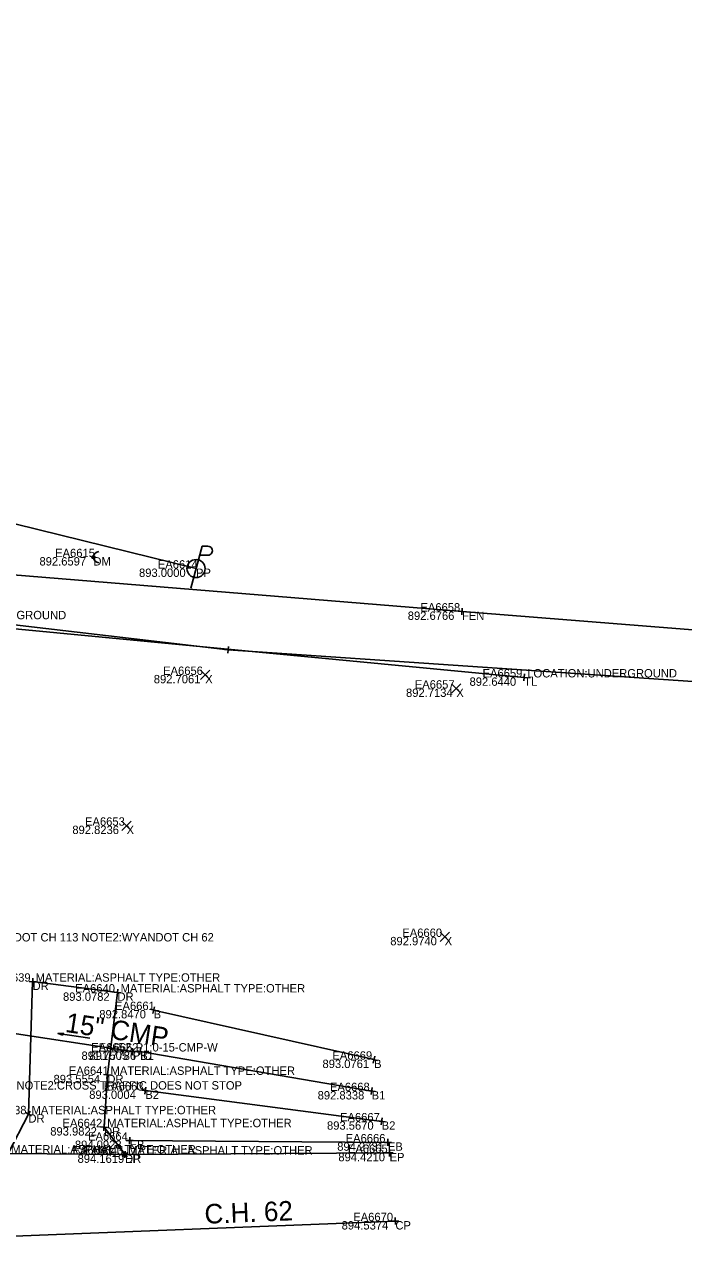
# Model space of a CAD drawing. Extents: x 179044 to 189691, y 286531 to 301257.
# Drawn here: x 180439.4 to 180533.9, y 300591.3 to 300769 of the extents above; entities that cross this region are included whole.
import ezdxf

# ---------------------------------------------------------------- set-up
doc = ezdxf.new("R2010")
doc.units = 0
for name, color, linetype in [('Default', 7, 'Continuous'), ('DR_X_Elev_Flow', 7, 'Continuous'), ('DR_X_Storm_Sewer', 7, 'Continuous'), ('DR_X_Text', 7, 'Continuous'), ('GK_Visualization', 7, 'Continuous'), ('PV_X_COP', 7, 'Continuous'), ('PV_X_Driveway', 7, 'Continuous'), ('PV_X_EOP', 7, 'Continuous'), ('PV_X_Shoulder_Aggregate', 7, 'Continuous'), ('RD_X_Fence', 7, 'Continuous'), ('SV_X_Break_Lines', 7, 'Continuous'), ('SV_X_Random_Point', 7, 'Continuous'), ('SV_X_Shot_Marker', 7, 'Continuous'), ('SV_X_Text_Comment', 7, 'Continuous'), ('SV_X_Text_Description', 7, 'Continuous'), ('SV_X_Text_Elevation', 7, 'Continuous'), ('SV_X_Text_Name', 7, 'Continuous'), ('UT_X_Electric', 7, 'Continuous'), ('UT_X_Electric_Cells', 7, 'Continuous'), ('UT_X_Misc_Cells', 7, 'Continuous'), ('UT_X_Telecom', 7, 'Continuous')]:
    doc.layers.add(name, color=color, linetype=linetype)

msp = doc.modelspace()

# ---------------------------------------------------------------- linework, layer by layer
at = {"layer": 'DR_X_Elev_Flow'}
for p, q in [((180454.37, 300621.65), (180455.37, 300621.65)), ((180454.85, 300621.65), (180454.9, 300621.65)), ((180454.87, 300622.15), (180454.87, 300621.15)), ((180454.87, 300621.68), (180454.87, 300621.63)), ((180454.87, 300621.65), (180454.87, 300621.65)), ((180454.87, 300621.65), (180454.87, 300621.65))]:
    msp.add_line(p, q, dxfattribs=at)
at = {"layer": 'DR_X_Storm_Sewer'}
msp.add_line((180454.87, 300621.65), (180427.21, 300625.82), dxfattribs=at)
at = {"layer": 'DR_X_Text'}
msp.add_line((180448.74, 300623.56), (180444.18, 300624.25), dxfattribs=at)
msp.add_lwpolyline([(180444.85, 300624), (180444.9, 300624.29), (180444.18, 300624.25)], close=True, dxfattribs=at)
at = {"layer": 'GK_Visualization'}
msp.add_line((180492.59, 300597.31), (180492.59, 300597.31), dxfattribs=at)
at = {"layer": 'PV_X_COP'}
msp.add_line((180492.59, 300597.31), (180492.59, 300597.31), dxfattribs=at)
msp.add_lwpolyline([(180387.7, 300594.07), (180431.76, 300594.91), (180492.59, 300597.31)], dxfattribs=at)
at = {"layer": 'PV_X_Driveway'}
msp.add_lwpolyline([(180437.01, 300607.02), (180439.92, 300612.65), (180440.51, 300631.67), (180452.7, 300630.12), (180451.25, 300618.3), (180450.77, 300610.79), (180453.78, 300606.87)], dxfattribs=at)
at = {"layer": 'PV_X_EOP'}
msp.add_lwpolyline([(180336.02, 300768.96), (180371.12, 300675.18), (180391.48, 300627.03), (180401.14, 300618.13), (180409.94, 300612.3), (180420.83, 300608.19), (180437.01, 300607.02), (180453.78, 300606.87), (180491.75, 300607.1)], dxfattribs=at)
at = {"layer": 'PV_X_Shoulder_Aggregate'}
msp.add_lwpolyline([(180454.44, 300608.87), (180491.51, 300608.61)], dxfattribs=at)
at = {"layer": 'RD_X_Fence'}
for points in [[(180413.11, 300692.06), (180502.15, 300684.78)], [(180502.15, 300684.78), (180578.58, 300678.71), (180657.49, 300671.91), (180764.58, 300663.83), (180831.65, 300658.07), (180898.21, 300649.16), (180980.03, 300636.76), (181057.42, 300625.97)]]:
    msp.add_lwpolyline(points, dxfattribs=at)
at = {"layer": 'SV_X_Break_Lines'}
for points in [[(180457.89, 300627.6), (180489.53, 300620.48)], [(180455.96, 300621.64), (180489.18, 300615.97)], [(180456.7, 300616.05), (180490.62, 300611.63)]]:
    msp.add_lwpolyline(points, dxfattribs=at)
at = {"layer": 'SV_X_Random_Point'}
for p, q in [((180464.62, 300675.02), (180465.95, 300676.35)), ((180464.62, 300676.35), (180465.95, 300675.02)), ((180500.66, 300673.05), (180502, 300674.39)), ((180500.66, 300674.39), (180502, 300673.05)), ((180453.33, 300653.38), (180454.67, 300654.72)), ((180453.33, 300654.72), (180454.67, 300653.38)), ((180498.99, 300637.42), (180500.33, 300638.76)), ((180498.99, 300638.76), (180500.33, 300637.42))]:
    msp.add_line(p, q, dxfattribs=at)
at = {"layer": 'SV_X_Shot_Marker'}
for p, q in [((180501.65, 300684.82), (180502.65, 300684.74)), ((180502.19, 300685.28), (180502.11, 300684.28)), ((180502.15, 300684.78), (180502.15, 300684.78)), ((180468.08, 300679.34), (180469.08, 300679.22)), ((180468.64, 300679.78), (180468.52, 300678.78)), ((180468.58, 300679.28), (180468.58, 300679.28)), ((180510.58, 300675.37), (180511.57, 300675.27)), ((180511.12, 300675.82), (180511.03, 300674.82)), ((180511.07, 300675.32), (180511.07, 300675.32)), ((180440.5, 300631.17), (180440.53, 300632.17)), ((180440.01, 300631.69), (180441.01, 300631.65)), ((180440.51, 300631.67), (180440.51, 300631.67)), ((180452.77, 300630.61), (180452.64, 300629.62)), ((180452.21, 300630.18), (180453.2, 300630.05)), ((180452.7, 300630.12), (180452.7, 300630.12)), ((180457.4, 300627.71), (180458.38, 300627.49)), ((180458, 300628.08), (180457.78, 300627.11)), ((180457.89, 300627.6), (180457.89, 300627.6)), ((180455.47, 300621.73), (180456.45, 300621.56)), ((180456.05, 300622.13), (180455.88, 300621.15)), ((180455.96, 300621.64), (180455.96, 300621.64)), ((180489.04, 300620.59), (180490.02, 300620.37)), ((180489.64, 300620.97), (180489.42, 300619.99)), ((180489.53, 300620.48), (180489.53, 300620.48)), ((180451.75, 300618.24), (180450.76, 300618.36)), ((180451.31, 300618.8), (180451.19, 300617.8)), ((180451.25, 300618.3), (180451.25, 300618.3)), ((180456.21, 300616.11), (180457.2, 300615.98)), ((180456.77, 300616.54), (180456.64, 300615.55)), ((180489.26, 300616.47), (180489.1, 300615.48)), ((180456.7, 300616.05), (180456.7, 300616.05)), ((180488.69, 300616.06), (180489.67, 300615.89)), ((180489.18, 300615.97), (180489.18, 300615.97)), ((180439.48, 300612.88), (180440.37, 300612.42)), ((180439.69, 300612.21), (180440.15, 300613.1)), ((180439.92, 300612.65), (180439.92, 300612.65)), ((180451.27, 300610.76), (180450.28, 300610.82)), ((180450.81, 300611.29), (180450.74, 300610.29)), ((180450.77, 300610.79), (180450.77, 300610.79)), ((180490.12, 300611.7), (180491.11, 300611.57)), ((180490.68, 300612.13), (180490.55, 300611.14)), ((180490.62, 300611.63), (180490.62, 300611.63)), ((180454.45, 300609.37), (180454.44, 300608.37)), ((180491.51, 300609.11), (180491.51, 300608.11)), ((180453.47, 300607.26), (180454.08, 300606.47)), ((180453.78, 300607.37), (180453.77, 300606.37)), ((180453.94, 300608.88), (180454.94, 300608.87)), ((180454.44, 300608.87), (180454.44, 300608.87)), ((180491.01, 300608.61), (180492.01, 300608.6)), ((180491.51, 300608.61), (180491.51, 300608.61)), ((180491.75, 300607.6), (180491.76, 300606.6)), ((180453.28, 300606.87), (180454.28, 300606.86)), ((180454.17, 300607.17), (180453.38, 300606.56)), ((180453.78, 300606.87), (180453.78, 300606.87)), ((180453.78, 300606.87), (180453.78, 300606.87)), ((180491.25, 300607.1), (180492.25, 300607.11)), ((180491.75, 300607.1), (180491.75, 300607.1)), ((180493.09, 300597.33), (180492.09, 300597.29)), ((180492.61, 300596.81), (180492.57, 300597.81)), ((180492.59, 300597.31), (180492.59, 300597.31))]:
    msp.add_line(p, q, dxfattribs=at)
at = {"layer": 'UT_X_Electric'}
msp.add_lwpolyline([(180111.81, 300685.43), (180395.56, 300707.8), (180463.97, 300690.94)], dxfattribs=at)
at = {"layer": 'UT_X_Electric_Cells'}
for p, q in [((180464.83, 300694.14), (180463.22, 300688.14)), ((180464.49, 300692.86), (180465.68, 300692.86)), ((180464.83, 300694.14), (180465.68, 300694.14))]:
    msp.add_line(p, q, dxfattribs=at)
msp.add_circle((180463.97, 300690.94), 1.3, dxfattribs=at)
msp.add_arc((180465.69, 300693.5), 0.638, 268.8767, 91.1233, dxfattribs=at)
at = {"layer": 'UT_X_Misc_Cells'}
msp.add_circle((180449.24, 300692.58), 0.2, dxfattribs=at)
msp.add_arc((180450.04, 300692.58), 0.8, 90, 270, dxfattribs=at)
at = {"layer": 'UT_X_Telecom'}
for points in [[(180390.05, 300708.28), (180399.57, 300693.15), (180404.36, 300688.28), (180411.7, 300685.92), (180468.58, 300679.28), (180578.09, 300671.82), (180656.6, 300666.72), (180686.36, 300663.45), (180690.68, 300657.04), (180703.63, 300629.93), (180709.13, 300611.67), (180711.81, 300592.05), (180711.93, 300578.12), (180722.74, 300551.74)], [(180393.91, 300703.5), (180400, 300691.59), (180410.26, 300688.49), (180423.4, 300683.67), (180511.07, 300675.32)]]:
    msp.add_lwpolyline(points, dxfattribs=at)

# ---------------------------------------------------------------- texts
at = {"layer": 'Default'}
msp.add_text('C.H. 62', height=2.8, rotation=2.2607, dxfattribs=at).set_placement((180465.24, 300596.93))
at = {"layer": 'DR_X_Text'}
msp.add_text('15" CMP', height=2.8, rotation=351.4248, dxfattribs=at).set_placement((180445.1, 300624.47))
at = {"layer": 'SV_X_Text_Comment'}
for s, height, p in [('DM', 1.2, (180449.24, 300691.38)), ('PP', 1.2, (180463.97, 300689.74)), ('FEN', 1.2, (180502.15, 300683.58)), ('TL', 0.06, (180468.58, 300679.22)), ('X', 1.2, (180465.29, 300674.48)), ('TL', 1.2, (180511.07, 300674.12)), ('X', 1.2, (180501.33, 300672.52)), ('X', 1.2, (180454, 300652.85)), ('X', 1.2, (180499.66, 300636.89)), ('DR', 1.2, (180440.51, 300630.47)), ('DR', 1.2, (180452.7, 300628.92)), ('B', 1.2, (180457.89, 300626.4)), ('P1=0-15-CMP-W', 0.06, (180454.87, 300621.59)), ('PIO', 1.2, (180454.87, 300620.45)), ('B1', 1.2, (180455.96, 300620.44)), ('B', 1.2, (180489.53, 300619.28)), ('DR', 1.2, (180451.25, 300617.1)), ('B2', 1.2, (180456.7, 300614.85)), ('B1', 1.2, (180489.18, 300614.77)), ('DR', 1.2, (180439.92, 300611.45)), ('DR', 1.2, (180450.77, 300609.59)), ('B2', 1.2, (180490.62, 300610.43)), ('EB', 1.2, (180454.44, 300607.67)), ('EB', 1.2, (180491.51, 300607.41)), ('DR', 1.2, (180453.78, 300605.67)), ('EP', 1.2, (180453.78, 300605.67)), ('EP', 1.2, (180491.75, 300605.9)), ('CP', 1.2, (180492.59, 300596.11))]:
    msp.add_text(s, height=height, dxfattribs=at).set_placement(p)
at = {"layer": 'SV_X_Text_Description'}
for s, height, p in [(' LOCATION:UNDERGROUND', 1.2, (180423.4, 300683.67)), (' LOCATION:UNDERGROUND', 1.2, (180511.07, 300675.32)), (' NOTE1:WYANDOT CH 113 NOTE2:WYANDOT CH 62', 1.2, (180426.76, 300637.44)), (' MATERIAL:ASPHALT TYPE:OTHER', 1.2, (180440.51, 300631.67)), (' MATERIAL:ASPHALT TYPE:OTHER', 1.2, (180452.7, 300630.12)), ('P1= 0-15-CMP-W', 0.06, (180454.87, 300621.65)), (' P1:0-15-CMP-W', 1.2, (180454.87, 300621.65)), (' MATERIAL:ASPHALT TYPE:OTHER', 1.2, (180451.25, 300618.3)), (' NOTE1:STOP NOTE2:CROSS TRAFFIC DOES NOT STOP', 1.2, (180427.15, 300616.19)), (' MATERIAL:ASPHALT TYPE:OTHER', 1.2, (180439.92, 300612.65)), (' MATERIAL:ASPHALT TYPE:OTHER', 1.2, (180450.77, 300610.79)), (' MATERIAL:ASPHALT TYPE:OTHER', 1.2, (180437.01, 300607.02)), (' MATERIAL:ASPHALT TYPE:OTHER', 1.2, (180437.01, 300607.02)), (' MATERIAL:ASPHALT TYPE:OTHER', 1.2, (180453.78, 300606.87)), (' MATERIAL:ASPHALT TYPE:OTHER', 1.2, (180453.78, 300606.87))]:
    msp.add_text(s, height=height, dxfattribs=at).set_placement(p)
at = {"layer": 'SV_X_Text_Elevation'}
for s, height, p in [('892.6597', 1.2, (180441.5, 300691.38)), ('893.0000', 1.2, (180455.79, 300689.74)), ('892.6766', 1.2, (180494.36, 300683.58)), ('892.6270', 0.06, (180468.19, 300679.22)), ('892.7061', 1.2, (180457.91, 300674.48)), ('892.6440', 1.2, (180503.23, 300674.12)), ('892.7134', 1.2, (180494.11, 300672.52)), ('892.8236', 1.2, (180446.22, 300652.85)), ('892.9740', 1.2, (180491.85, 300636.89)), ('893.0782', 1.2, (180444.88, 300628.92)), ('892.8470', 1.2, (180450.09, 300626.4)), ('891.7505', 1.2, (180447.53, 300620.45)), ('891.7786', 1.2, (180448.68, 300620.44)), ('891.75', 0.06, (180454.61, 300621.59)), ('893.0761', 1.2, (180482.12, 300619.28)), ('893.5554', 1.2, (180443.52, 300617.1)), ('893.0004', 1.2, (180448.64, 300614.85)), ('892.8338', 1.2, (180481.43, 300614.77)), ('893.9822', 1.2, (180443.05, 300609.59)), ('893.5670', 1.2, (180482.77, 300610.43)), ('894.0928', 1.2, (180446.59, 300607.67)), ('894.2731', 1.2, (180484.24, 300607.41)), ('894.1619', 1.2, (180446.97, 300605.67)), ('894.1619', 1.2, (180446.97, 300605.67)), ('894.4210', 1.2, (180484.4, 300605.9)), ('894.5374', 1.2, (180484.87, 300596.11))]:
    msp.add_text(s, height=height, dxfattribs=at).set_placement(p)
at = {"layer": 'SV_X_Text_Name'}
for s, height, p in [('EA6615', 1.2, (180443.75, 300692.58)), ('EA6614', 1.2, (180458.49, 300690.94)), ('EA6658', 1.2, (180496.18, 300684.78)), ('SV5048', 0.06, (180468.28, 300679.28)), ('EA6656', 1.2, (180459.25, 300675.68)), ('EA6659', 1.2, (180505.1, 300675.32)), ('EA6657', 1.2, (180495.37, 300673.72)), ('EA6653', 1.2, (180448.04, 300654.05)), ('EA6660', 1.2, (180493.58, 300638.09)), ('EA6639', 1.2, (180434.52, 300631.67)), ('EA6640', 1.2, (180446.63, 300630.12)), ('EA6661', 1.2, (180452.35, 300627.6)), ('EA6652', 1.2, (180448.92, 300621.65)), ('EA6662', 1.2, (180449.99, 300621.64)), ('EA6652', 0.06, (180454.57, 300621.65)), ('EA6669', 1.2, (180483.54, 300620.48)), ('EA6641', 1.2, (180445.72, 300618.3)), ('EA6663', 1.2, (180450.72, 300616.05)), ('EA6668', 1.2, (180483.19, 300615.97)), ('EA6638', 1.2, (180433.93, 300612.65)), ('EA6667', 1.2, (180484.64, 300611.63)), ('EA6642', 1.2, (180444.81, 300610.79)), ('EA6664', 1.2, (180448.47, 300608.87)), ('EA6666', 1.2, (180485.45, 300608.61)), ('EA6643_1', 1.2, (180446.25, 300606.87)), ('EA6643', 1.2, (180447.81, 300606.87)), ('EA6665', 1.2, (180485.77, 300607.1)), ('EA6670', 1.2, (180486.54, 300597.31))]:
    msp.add_text(s, height=height, dxfattribs=at).set_placement(p)

doc.saveas('drawing.dxf')
